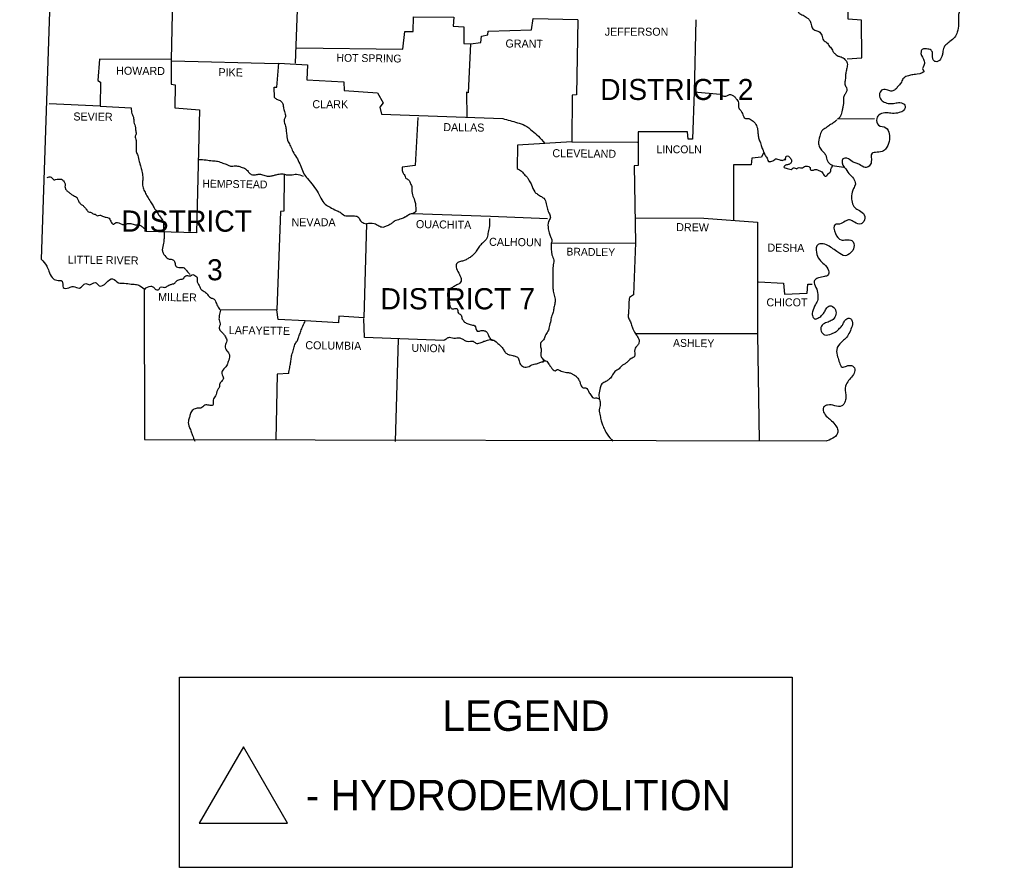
# Model space of a CAD drawing. Extents: x -17668 to 16999, y -17303 to 5867.
# Drawn here: x -17668 to -14783, y 1636 to 4141 of the extents above; entities that cross this region are included whole.
import ezdxf

# ---------------------------------------------------------------- set-up
doc = ezdxf.new("R2010")
doc.units = 0
for name, color, linetype in [('1', 7, 'Continuous'), ('2', 7, 'Continuous'), ('3', 7, 'Continuous'), ('48', 7, 'Continuous')]:
    doc.layers.add(name, color=color, linetype=linetype)

msp = doc.modelspace()

# ---------------------------------------------------------------- linework, layer by layer
at = {"layer": '1'}
msp.add_line((-15250.6, 3847.5), (-15140.6, 3849.1), dxfattribs=at)
for points in [[(-17667.8, 5841.4), (-17553.9, 4926.7), (-17603.4, 3433.6)], [(-15220.9, 4025.3), (-15178, 4028), (-15178.6, 4139.7), (-15218.7, 4142.5), (-15216.5, 4361), (-15251.2, 4365.9), (-15252.3, 4512.9), (-14782.8, 4516.2)], [(-16840.6, 4354.9), (-16853.3, 4012.1)], [(-17213.8, 4294.4), (-17219.8, 4023.6), (-17431.7, 4024.2), (-17436.7, 3961.4), (-17428.9, 3955.9), (-17429.5, 3885.5), (-17579.7, 3892.1)], [(-16849.4, 4057.7), (-16534.6, 4053.3), (-16528.6, 4105.6), (-16503.8, 4105.6), (-16503.3, 4149.6), (-16384.4, 4148), (-16385.5, 4121.6), (-16354.7, 4119.4), (-16354.7, 4070.9), (-16334.8, 4069.3)], [(-16334.8, 4069.3), (-16304, 4073.7), (-16301.8, 4092.4), (-16283.7, 4095.7), (-16282.6, 4106.7), (-16154.3, 4110.6), (-16149.4, 4144.1), (-16017.8, 4141.9)], [(-16017.8, 4140.8), (-16021.1, 3918.5), (-16033.8, 3917.9), (-16035.5, 3779.8)], [(-15668.9, 4140.3), (-15673.3, 3927.3), (-15596.8, 3921.2)], [(-16334.8, 4069.3), (-16341.4, 3925.1), (-16346.4, 3926.7), (-16345.9, 3851.9)], [(-17219.8, 4023.6), (-17219.8, 3950.4), (-17207.7, 3948.2), (-17208.8, 3880), (-17136.2, 3874.5), (-17145, 3510.7), (-17294.7, 3514.5)], [(-17218.7, 4019.8), (-16903.9, 4011.5)], [(-16914.4, 3910.8), (-16915.5, 3941.1), (-16906.7, 3941.6), (-16901.2, 4012.6), (-16816.4, 4007.1), (-16818.6, 3963.6), (-16709.1, 3957.6), (-16708.5, 3931.2), (-16609.5, 3925.1), (-16592.4, 3895.4), (-16602.9, 3882.2), (-16597.9, 3861.8), (-16239.1, 3848.6)], [(-15673.3, 3927.3), (-15678.3, 3787.5), (-15690.9, 3787.5), (-15693.1, 3809), (-15839.5, 3809), (-15839.5, 3778.2)], [(-17429.5, 3885.5), (-17338.1, 3880)], [(-16490, 3851.4), (-16498.3, 3709.9), (-16536.3, 3705.5)], [(-16035.5, 3779.8), (-16115.8, 3774.9)], [(-16035.5, 3779.8), (-15840.6, 3778.7)], [(-16114.7, 3774.9), (-16196.2, 3769.9), (-16196.7, 3701.1)], [(-15839.5, 3778.7), (-15839, 3709.9), (-15850.5, 3709.4), (-15847.2, 3481)], [(-15467.5, 3749.5), (-15474.1, 3734.7), (-15503.3, 3731.9), (-15504.9, 3712.1), (-15557.2, 3712.1), (-15557.7, 3547.6)], [(-15405.8, 3725.3), (-15404.2, 3727), (-15402.5, 3728.6), (-15402.5, 3728.6)], [(-16885.2, 3684.6), (-16886.3, 3575.1), (-16896.2, 3574), (-16907.2, 3283.9)], [(-16503.8, 3568.5), (-16276, 3560.2), (-16107, 3553.6)], [(-15848.9, 3555.8), (-15644.7, 3554.2), (-15486.2, 3542.1)], [(-16642.5, 3537.6), (-16649.6, 3260.3), (-16723.9, 3265.2), (-16724.5, 3244.9), (-16823.6, 3250.9)], [(-15486.2, 3542.1), (-15486.2, 3212.9), (-15481.8, 2896.5)], [(-16096, 3480.4), (-15847.2, 3481)], [(-15847.2, 3481), (-15852.7, 3328), (-15864.8, 3320.3)], [(-15483.4, 3366.5), (-15409.7, 3362.1), (-15406.4, 3330.2), (-15339.8, 3332.4), (-15337.1, 3359.3), (-15324.4, 3359.3)], [(-17299.1, 3345), (-17298, 2899.8), (-15280.9, 2896.5)], [(-16823.6, 3250.9), (-16903.4, 3255.3), (-16907.2, 3283.9), (-17074, 3282.3)], [(-16413.5, 3193.1), (-16648.5, 3201.9), (-16649.6, 3257.5)], [(-15843.9, 3213.5), (-15486.2, 3213.5)], [(-16548.4, 3197), (-16557.2, 2894.8)], [(-16872, 3095.2), (-16906.1, 3093), (-16910, 2899.2)]]:
    msp.add_lwpolyline(points, dxfattribs=at)
for points in [[(-14817.5, 4383), (-14830.2, 4367), (-14848.9, 4376.9), (-14848.9, 4390.1), (-14846.1, 4403.9), (-14852.7, 4412.7), (-14864.3, 4408.9), (-14864.3, 4391.8), (-14865.4, 4375.3), (-14868.7, 4351.6), (-14861, 4344.5), (-14843.4, 4342.3), (-14830.7, 4339), (-14823, 4326.3), (-14823.6, 4310.9), (-14829.6, 4296), (-14838.4, 4283.9), (-14852.2, 4279.5), (-14863.2, 4286.7), (-14867.6, 4301), (-14872.6, 4313.6), (-14881.9, 4323), (-14891.8, 4312.5), (-14894, 4293.3), (-14893.5, 4276.8), (-14893.5, 4254.2), (-14879.2, 4239.3), (-14870.4, 4222.3), (-14873.1, 4206.9), (-14883.6, 4188.7), (-14888, 4172.8), (-14892.4, 4151.3), (-14891.8, 4127.6), (-14895.7, 4104.5), (-14903.4, 4089.1), (-14917.7, 4076.4), (-14927, 4068.2), (-14934.7, 4059.9), (-14938.6, 4043.4), (-14941.3, 4031.9), (-14951.8, 4018.1), (-14960.1, 4017), (-14966.7, 4022.5), (-14968.9, 4031.9), (-14968.9, 4041.2), (-14973.3, 4050.6), (-14987, 4054.4), (-14998, 4053.9), (-15003, 4046.2), (-14995.8, 4024.7), (-14993.1, 4011), (-14996.9, 3992.2), (-14994.7, 3990), (-15014.5, 3979.6), (-15030.5, 3977.9), (-15043.7, 3974.1), (-15056.4, 3965.8), (-15062.4, 3953.7), (-15071.2, 3943.8), (-15078.9, 3934.5), (-15089.4, 3930.1), (-15101, 3932.3), (-15116.4, 3933.9), (-15125.2, 3922.9), (-15122.4, 3906.9), (-15112, 3897.6), (-15096.5, 3893.2), (-15080.6, 3894.3), (-15065.2, 3895.9), (-15050.9, 3888.2), (-15053.6, 3873.4), (-15067.4, 3866.2), (-15087.7, 3864), (-15104.3, 3865.7), (-15124.1, 3861.3), (-15134, 3848.6), (-15128.5, 3829.3), (-15107, 3821.6), (-15097.1, 3803.5), (-15096.5, 3786.4), (-15103.7, 3763.8), (-15113.6, 3753.4), (-15132.9, 3749), (-15147.7, 3746.2), (-15149.9, 3720.9), (-15156.5, 3708.3), (-15168.1, 3704.4), (-15184.6, 3712.7), (-15194.5, 3716.5), (-15206.6, 3722), (-15222, 3731.4), (-15233.6, 3729.7), (-15230.3, 3705.5), (-15229.2, 3704.4), (-15216, 3686.2), (-15202.8, 3671.9), (-15196.7, 3654.9)], [(-15387.7, 4205.8), (-15386, 4183.2), (-15372.8, 4179.9), (-15367.3, 4173.9), (-15364.6, 4161.2), (-15355.2, 4155.7), (-15342.6, 4148), (-15334.9, 4142.5), (-15329.3, 4133.7), (-15326, 4119.4), (-15317.2, 4110), (-15305.1, 4105.6), (-15296.3, 4095.2), (-15290.8, 4080.3), (-15282, 4073.7), (-15273.2, 4062.1), (-15268.8, 4057.2), (-15261.1, 4044), (-15253.4, 4037.4), (-15247.9, 4033.5), (-15239.1, 4030.8), (-15228.1, 4023.6), (-15220.9, 4012.6), (-15220.9, 4004.3), (-15223.7, 3991.7), (-15225.9, 3978.5), (-15227, 3963.6), (-15228.1, 3950.4), (-15223.1, 3939.4), (-15225.9, 3922.9), (-15231.4, 3914.1), (-15231.9, 3902), (-15233.6, 3883.8), (-15235.8, 3873.4), (-15240.7, 3856.3), (-15247.9, 3847.5)], [(-16914.4, 3910.8), (-16905.6, 3905.3), (-16895.1, 3900.3), (-16889.6, 3892.1), (-16887.4, 3879.4), (-16883.5, 3865.7), (-16882.4, 3851.4), (-16885.7, 3843.6), (-16881.3, 3826), (-16879.7, 3813.9), (-16878, 3799.6), (-16873.6, 3780.4), (-16866.5, 3767.1), (-16859.9, 3751.2), (-16848.9, 3734.1), (-16839.5, 3715.4), (-16835.1, 3705.5), (-16826.9, 3685.1), (-16816.4, 3671.4), (-16799.9, 3650.5), (-16785, 3629), (-16776.8, 3613), (-16764.1, 3595.4), (-16749.8, 3586.6), (-16731.6, 3577.3), (-16720.1, 3571.8), (-16706.9, 3562.4), (-16689.8, 3561.3), (-16677.2, 3561.3), (-16665.6, 3556.4), (-16660.1, 3546.5), (-16650.2, 3539.9), (-16642.5, 3537.6)], [(-15596.8, 3921.2), (-15588.6, 3915.7), (-15577, 3916.3), (-15569.3, 3919.6), (-15563.2, 3919), (-15555, 3914.1), (-15549.5, 3907.5), (-15545.6, 3902.5), (-15542.9, 3894.8), (-15542.9, 3887.7), (-15540.1, 3877.8), (-15536.8, 3873.9), (-15532.4, 3866.8), (-15529.7, 3860.2), (-15528, 3855.8), (-15522, 3848.6), (-15516.5, 3849.1), (-15511.5, 3848.6), (-15504.9, 3844.7), (-15495, 3837), (-15493.4, 3834.8), (-15486.7, 3820.5), (-15485.6, 3811.7), (-15484.5, 3800.2), (-15482.3, 3789.2), (-15477.9, 3777.1), (-15475.7, 3768.8), (-15470.8, 3757.2), (-15467.5, 3749.5), (-15463.1, 3739.6), (-15456.5, 3728.6), (-15453.7, 3722), (-15444.4, 3722.6), (-15437.8, 3725.3), (-15432.8, 3729.7), (-15426.8, 3729.2), (-15420.2, 3727), (-15411.4, 3725.3), (-15405.8, 3728.6), (-15403.1, 3730.8), (-15402.5, 3735.8), (-15397.6, 3738.5), (-15392.1, 3734.7), (-15386, 3725.9), (-15386, 3720.4), (-15388.2, 3717.1), (-15395.4, 3712.7), (-15405.3, 3709.4), (-15408, 3705.5), (-15398.7, 3701.1), (-15383.8, 3700), (-15380, 3703.3), (-15370.1, 3700.6), (-15366.2, 3703.3), (-15353, 3702.8), (-15347, 3707.2), (-15334.9, 3706.6), (-15331, 3703.9), (-15331, 3698.9), (-15321.1, 3696.7), (-15313.9, 3698.4), (-15304.6, 3695.6), (-15296.3, 3691.2), (-15291.9, 3685.1), (-15286.4, 3678.5), (-15281.5, 3680.2), (-15277.6, 3685.1), (-15269.4, 3693.9), (-15269.4, 3699.5), (-15267.2, 3703.3), (-15264.4, 3708.8)], [(-17338.1, 3880), (-17335.4, 3863.5), (-17330.4, 3849.1), (-17329.9, 3838.1), (-17324.9, 3821.6), (-17324.9, 3815.6), (-17323.3, 3803.5), (-17325.5, 3796.9), (-17322.7, 3783.7), (-17323.3, 3773.8), (-17323.3, 3765.5), (-17322.7, 3751.7), (-17318.3, 3739.6), (-17313.9, 3721.5), (-17311.2, 3712.1), (-17306.8, 3697.8), (-17304, 3680.2), (-17303.5, 3667), (-17304.6, 3654.9), (-17301.3, 3641.1), (-17295.2, 3627.4), (-17287.5, 3614.1), (-17278.2, 3599.3), (-17271.5, 3587.7), (-17263.3, 3575.1), (-17256.7, 3564.6), (-17246.8, 3551.4), (-17242.4, 3540.4), (-17242.4, 3525), (-17240.2, 3510.7), (-17240.7, 3494.7), (-17241.8, 3480.4), (-17245.7, 3460.6), (-17242.9, 3451.2), (-17232.5, 3437.5), (-17225.9, 3433.6), (-17214.3, 3431.4), (-17208.8, 3423.7), (-17205.5, 3412.2), (-17193.9, 3408.3), (-17181.3, 3407.2), (-17175.2, 3400.6), (-17167, 3391.8), (-17164.2, 3387.4)], [(-16239.1, 3848.6), (-16196.2, 3836.5), (-16174.1, 3828.2), (-16152.1, 3812.3), (-16134, 3796.3), (-16115.8, 3776)], [(-15251.7, 3844.2), (-15263.3, 3834.8), (-15273.2, 3829.3), (-15283.7, 3821.6), (-15296.3, 3812.3), (-15302.4, 3796.3), (-15305.7, 3774.3), (-15301.3, 3761.1), (-15291.4, 3749.5), (-15284.8, 3740.2), (-15279.8, 3723.7), (-15267.7, 3712.1), (-15263.9, 3710.5)], [(-17137.3, 3728.1), (-17116.3, 3726.4), (-17097.1, 3724.2), (-17082.2, 3722.6), (-17066.8, 3717.1), (-17053.1, 3712.1), (-17044.3, 3708.3), (-17029.4, 3709.4), (-17016.7, 3706.6), (-17002.4, 3701.7), (-16992, 3692.3), (-16985.4, 3685.1), (-16972.7, 3682.4), (-16962.2, 3684), (-16949.6, 3682.9), (-16935.3, 3678.5), (-16923.7, 3679.1), (-16914.4, 3681.3), (-16903.4, 3684), (-16889.6, 3685.1), (-16879.1, 3682.9), (-16865.4, 3682.4), (-16849.4, 3684), (-16829.6, 3678.5)], [(-16536.3, 3705.5), (-16536.3, 3695), (-16532.4, 3685.1), (-16528.6, 3680.7), (-16526.9, 3673.6), (-16522, 3670.3), (-16514.8, 3663.7), (-16511, 3654.3), (-16508.2, 3648.3), (-16508.2, 3640.6), (-16507.7, 3632.9), (-16506.6, 3623.5), (-16500, 3607), (-16498.3, 3600.4), (-16497.2, 3594.9), (-16496.6, 3585.5), (-16496.6, 3574.5), (-16503.8, 3568.5)], [(-16196.7, 3701.1), (-16184, 3692.8), (-16173.6, 3681.8), (-16165.9, 3673.6), (-16160.9, 3664.2), (-16154.3, 3653.2), (-16145, 3632.3), (-16136.7, 3625.2), (-16125.2, 3618), (-16118, 3613), (-16110.9, 3597.1), (-16107.5, 3581.1), (-16101.5, 3566.8), (-16098.7, 3555.8), (-16103.7, 3544.8), (-16104.8, 3522.8), (-16101.5, 3507.9), (-16097.1, 3496.9), (-16094.3, 3484.3), (-16096, 3480.4)], [(-17586.3, 3674.7), (-17574.2, 3675.2), (-17566, 3668.1), (-17561, 3668.6), (-17552.2, 3669.7), (-17544, 3669.2), (-17537.9, 3664.2), (-17533, 3655.4), (-17533.5, 3647.2), (-17533, 3643.9), (-17529.1, 3636.7), (-17522.5, 3631.2), (-17515.4, 3625.7), (-17508.7, 3621.3), (-17497.7, 3614.1), (-17496.6, 3611.9), (-17492.2, 3603.1), (-17486.7, 3596), (-17480.1, 3591.6), (-17473, 3583.9), (-17469.7, 3580.6), (-17464.2, 3572.9), (-17458.1, 3572.3), (-17449.9, 3567.4), (-17443.8, 3565.7), (-17437.2, 3561.3), (-17430.6, 3563.5), (-17422.3, 3560.2), (-17411.3, 3556.9), (-17405.3, 3555.8), (-17398.1, 3545.4), (-17391, 3536.5), (-17382.2, 3541.5), (-17365.7, 3536.5), (-17355.2, 3536), (-17345.8, 3538.7), (-17338.7, 3538.2), (-17325.5, 3534.9), (-17317.2, 3534.9), (-17308.4, 3531.6), (-17300.2, 3525), (-17294.7, 3517.8), (-17294.7, 3514.5)], [(-15196.7, 3654.9), (-15202.2, 3642.2), (-15208.3, 3620.2), (-15206.6, 3601.5), (-15198.4, 3585.5), (-15185.2, 3576.7), (-15170.8, 3564.1), (-15171.9, 3544.8), (-15180.2, 3537.6), (-15199.5, 3542.6), (-15214.3, 3549.2), (-15227, 3545.4), (-15244, 3537.1), (-15256.7, 3535.4), (-15256.2, 3509), (-15239.1, 3490.3), (-15224.2, 3490.3), (-15207.2, 3488.1), (-15201.1, 3468.3), (-15211, 3451.8), (-15227.5, 3443.5), (-15248.4, 3453.4), (-15263.3, 3463.9), (-15278.2, 3473.8), (-15296.9, 3478.8), (-15307.3, 3476.6), (-15312.3, 3453.4), (-15303.5, 3432.5), (-15289.2, 3418.2), (-15276, 3399.5), (-15278.2, 3385.8), (-15288.1, 3381.9), (-15305.7, 3378), (-15316.1, 3372.5), (-15318.9, 3368.1), (-15313.4, 3349.4), (-15308.4, 3329.1), (-15308.4, 3313.7), (-15314.5, 3299.3), (-15323.8, 3277.3), (-15322.7, 3263), (-15316.1, 3256.4), (-15307.9, 3258.6), (-15296.9, 3266.3), (-15289.7, 3275.1), (-15283.7, 3286.1), (-15272.1, 3295.5), (-15257.8, 3287.2), (-15254.5, 3270.2), (-15262.8, 3255.3), (-15274.3, 3248.7), (-15288.6, 3243.2), (-15299.1, 3231.1), (-15296.3, 3216.8), (-15288.1, 3209.1), (-15267.7, 3212.9), (-15253.9, 3219), (-15246.2, 3226.7), (-15236.9, 3236.1), (-15231.9, 3245.4), (-15224.8, 3255.3), (-15212.1, 3258.1), (-15206.1, 3249.8), (-15208.3, 3231.1), (-15216, 3213.5), (-15226.4, 3198.6), (-15238, 3188.2), (-15252.3, 3165.6), (-15249.5, 3144.7), (-15244, 3127.6), (-15236.3, 3114.4), (-15223.1, 3117.2), (-15208.3, 3118.8), (-15199.5, 3111.7), (-15200.6, 3096.3), (-15211.6, 3081.4), (-15222, 3067.1), (-15227.5, 3047.3), (-15225.3, 3033.5), (-15225.3, 3020.9), (-15229.7, 3007.1), (-15237.4, 2999.4), (-15257.8, 3000), (-15279.3, 3002.2), (-15290.8, 2995.6), (-15288.6, 2976.8), (-15276, 2963.1), (-15267.2, 2955.9), (-15254.5, 2940.5), (-15249, 2927.9), (-15250.6, 2916.8), (-15258.4, 2907.5), (-15280.9, 2896.5)], [(-16514.3, 3566.3), (-16528.6, 3556.9), (-16539.6, 3552.5), (-16547.8, 3549.8), (-16555.5, 3547.6), (-16565.4, 3541), (-16573.1, 3535.4), (-16583.6, 3530.5), (-16593.5, 3527.2), (-16605.6, 3531), (-16612.2, 3534.9), (-16619.4, 3537.6), (-16642.5, 3537.6)], [(-16528.6, 3556.9), (-16514.3, 3566.3), (-16503.8, 3568.5)], [(-16278.2, 3553.6), (-16279.3, 3526.1), (-16283.1, 3509), (-16287, 3493.6), (-16295.2, 3484.8), (-16304, 3476), (-16312.3, 3466.1), (-16319.4, 3454), (-16326.6, 3446.3), (-16335.9, 3438.6), (-16345.3, 3433.1), (-16355.8, 3428.1), (-16367.3, 3425.4), (-16375.6, 3419.3), (-16376.1, 3406.1), (-16366.8, 3387.4), (-16363.5, 3378.6), (-16362.4, 3368.1), (-16366.2, 3362.1), (-16375, 3357.1), (-16385.5, 3351.1), (-16394.8, 3345.6), (-16401.4, 3336.2), (-16402.5, 3323.6), (-16398.1, 3308.7), (-16396.5, 3299.9), (-16389.3, 3286.1), (-16383.8, 3286.7), (-16373.9, 3286.1), (-16372.8, 3283.4), (-16372.3, 3280.6), (-16370.1, 3273.5), (-16361.8, 3267.4), (-16360.7, 3261.9), (-16355.8, 3251.5), (-16347.5, 3244.3), (-16341.4, 3242.1), (-16328.8, 3238.3), (-16322.2, 3236.6), (-16315, 3220.6), (-16306.2, 3221.2), (-16299.6, 3222.3), (-16288.6, 3219.5), (-16283.7, 3212.9), (-16278.7, 3201.9), (-16272.1, 3194.2), (-16267.7, 3194.2)], [(-16096, 3480.4), (-16093.8, 3446.3), (-16088.8, 3429.8), (-16090.5, 3412.2), (-16091, 3395.1), (-16091, 3379.7), (-16091, 3364.8), (-16091, 3349.4), (-16089.9, 3338.4), (-16086.1, 3322.5), (-16084.4, 3307.6), (-16087.7, 3293.3), (-16089.4, 3280.1), (-16093.8, 3266.9), (-16097.6, 3252), (-16102, 3232.8), (-16105.9, 3220.1), (-16113.6, 3206.9), (-16118.6, 3194.8), (-16126.3, 3187.1), (-16127.4, 3173.9), (-16125.7, 3161.8), (-16126.8, 3150.7), (-16123, 3140.3), (-16113.1, 3133.1)], [(-17603.4, 3433.6), (-17587.5, 3412.7), (-17580.8, 3397.9), (-17571.5, 3378.6), (-17557.7, 3370.9), (-17541.8, 3368.1), (-17538.5, 3349.4), (-17522, 3348.9), (-17508.7, 3352.7), (-17490.6, 3347.8), (-17471.3, 3361), (-17460.3, 3357.7), (-17444.4, 3364.3), (-17432.3, 3354.4), (-17411.3, 3363.2), (-17392.6, 3375.3), (-17375, 3363.7), (-17358, 3362.1), (-17337.6, 3359.3), (-17321.6, 3358.2), (-17307.3, 3351.1), (-17296.9, 3343.9), (-17299.1, 3345)], [(-17299.1, 3345), (-17279.8, 3353.3), (-17271.5, 3350.5), (-17264.4, 3343.4), (-17256.1, 3343.4), (-17251.7, 3350), (-17243.5, 3350.5), (-17236.9, 3350), (-17229.7, 3354.4), (-17223.7, 3357.1), (-17215.4, 3359.9), (-17209.4, 3362.1), (-17203.9, 3368.1), (-17193.9, 3373.1), (-17182.4, 3376.9), (-17179.1, 3382.4), (-17173.6, 3384.7), (-17162.6, 3384.1), (-17155.4, 3387.4), (-17149.4, 3384.7), (-17143.9, 3380.8), (-17142.8, 3366.5), (-17138.4, 3358.8), (-17131.8, 3345), (-17122.4, 3337.9), (-17113.6, 3330.7), (-17110.3, 3326.3), (-17100.9, 3318.1), (-17092.7, 3315.3), (-17088.8, 3309.3), (-17082.8, 3294.9), (-17074, 3282.3)], [(-15864.8, 3320.3), (-15866.5, 3303.2), (-15867, 3287.2), (-15868.1, 3271.8), (-15868.1, 3260.3), (-15861.5, 3247.6), (-15857.7, 3235.5), (-15853.8, 3225), (-15846.1, 3211.3), (-15839, 3200.8), (-15836.8, 3186), (-15841.2, 3178.3), (-15849.4, 3166.7), (-15850, 3145.8), (-15859.9, 3139.2), (-15872.5, 3128.2), (-15879.7, 3123.2), (-15887.4, 3118.3), (-15895.7, 3109.5), (-15907.8, 3101.2), (-15916.6, 3087.5), (-15926.5, 3077), (-15934.7, 3071.5), (-15946.3, 3064.3), (-15951.2, 3053.3), (-15955.1, 3033), (-15953.4, 3018.1), (-15951.2, 3004.9), (-15954, 2988.4), (-15951.2, 2970.2), (-15948.5, 2955.9), (-15944.1, 2943.3), (-15938, 2929), (-15930.3, 2915.7), (-15913.8, 2895.4)], [(-17074, 3282.3), (-17077.3, 3266.3), (-17077.8, 3253.7), (-17075.1, 3238.8), (-17077.8, 3231.7), (-17073.4, 3221.2), (-17065.2, 3212.9), (-17059.1, 3204.1), (-17055.3, 3191.5), (-17060.2, 3177.2), (-17054.7, 3162.3), (-17049.8, 3156.8), (-17047, 3148), (-17050.9, 3130.9), (-17055.8, 3118.3), (-17066.8, 3105.6), (-17070.1, 3099.6), (-17068.5, 3091.3), (-17065.7, 3078.1), (-17068.5, 3074.3), (-17075.6, 3064.9), (-17077.8, 3054.4), (-17082.8, 3045.6), (-17088.3, 3029.7), (-17095.4, 3016.5), (-17096.5, 3001.6), (-17107.5, 3001.6), (-17120.2, 3001.6), (-17131.8, 2993.3), (-17142.2, 2992.8), (-17154.9, 2987.8), (-17162.6, 2977.4), (-17165.3, 2965.8), (-17168.6, 2954.8), (-17165.3, 2936.1), (-17160.4, 2922.9), (-17156.5, 2912.4), (-17149.9, 2895.4)], [(-16872, 3095.2), (-16869.2, 3112.8), (-16866.5, 3126.5), (-16864.8, 3139.7), (-16861.5, 3154.6), (-16856.6, 3170.6), (-16852.2, 3183.8), (-16846.1, 3193.1), (-16842.3, 3204.1), (-16837.3, 3217.3), (-16832.4, 3231.1), (-16823.6, 3248.7)], [(-16413.5, 3193.1), (-16404.7, 3199.2), (-16396.5, 3202.5), (-16388.2, 3200.8), (-16379.4, 3199.7), (-16371.7, 3200.8), (-16361.8, 3199.2), (-16353.6, 3194.2), (-16344.2, 3190.4), (-16334.8, 3190.4), (-16326.6, 3190.4), (-16319.4, 3185.4), (-16306.2, 3186), (-16295.2, 3190.4), (-16284.2, 3193.7), (-16269.4, 3195.3), (-16256.1, 3186), (-16246.8, 3178.3), (-16239.1, 3169.5), (-16233.6, 3159.6), (-16227.5, 3154.1), (-16217.6, 3150.2), (-16209.9, 3148.5), (-16200.6, 3145.8), (-16195.6, 3143.6), (-16191.2, 3133.1), (-16184, 3118.8), (-16170.3, 3113.9), (-16153.2, 3120.5), (-16139.5, 3124.3), (-16129.6, 3127.6), (-16123.5, 3129.8), (-16118, 3130.4), (-16119.7, 3131.5), (-16113.1, 3133.1), (-16107, 3128.7), (-16103.1, 3122.7), (-16096.5, 3113.9), (-16090.5, 3106.2), (-16084.4, 3103.4), (-16078.4, 3106.7), (-16070.1, 3104), (-16063, 3101.2), (-16054.7, 3099), (-16047.6, 3098.5), (-16038.2, 3096.3), (-16031, 3092.4), (-16024.4, 3088.6), (-16017.8, 3081.4), (-16011.2, 3070.4), (-16009, 3061.6), (-16001.3, 3052.8), (-15994.2, 3052.8), (-15983.7, 3038.5), (-15979.9, 3033), (-15971.6, 3023.1), (-15965.6, 3023.1), (-15954, 3020.9)]]:
    msp.add_spline(points, degree=3, dxfattribs=at)
at = {"layer": '3'}
msp.add_line((-15265.5, 3709.9), (-15230.8, 3705.5), dxfattribs=at)
at = {"layer": '48'}
for p, q in [((-17005.9, 1992.2), (-17136.5, 1766)), ((-16875.3, 1766), (-17005.9, 1992.2)), ((-17136.5, 1766), (-16875.3, 1766))]:
    msp.add_line(p, q, dxfattribs=at)
msp.add_lwpolyline([(-17194.5, 2198.1), (-15383.9, 2198.1), (-15383.9, 1635.5), (-17194.5, 1635.5)], close=True, dxfattribs=at)

# ---------------------------------------------------------------- texts
at = {"layer": '2'}
for s, height, p in [('JEFFERSON', 23.67, (-15938, 4093.5)), ('CLARK', 23.67, (-16802, 3879.3)), ('LINCOLN', 23.11, (-15785, 3746.2)), ('NEVADA', 23.67, (-16863.7, 3530.5)), ('CHICOT', 23.67, (-15459.8, 3293.8))]:
    msp.add_text(s, height=height, dxfattribs=at).set_placement(p)
for s, height, rotation, p in [('GRANT', 23.67, 359.4032, (-16231.4, 4058.8)), ('HOT SPRING', 23.11, 359.2216, (-16731.1, 4017)), ('HOWARD', 23.67, 359.5145, (-17382.2, 3978.5)), ('PIKE', 23.66, 359.0452, (-17080, 3974.1)), ('SEVIER', 23.67, 359.4271, (-17508.7, 3843.1)), ('DALLAS', 23.66, 359.2462, (-16415.2, 3811.7)), ('CLEVELAND', 23.67, 359.3377, (-16092.7, 3734.7)), ('HEMPSTEAD', 23.11, 359.1885, (-17127.4, 3645)), ('OUACHITA', 23.67, 359.2043, (-16496.1, 3525)), ('DREW', 23.66, 359.2258, (-15726.7, 3516.2)), ('CALHOUN', 23.67, 359.3634, (-16279.8, 3472.7)), ('BRADLEY', 23.11, 359.1449, (-16051.4, 3444.1)), ('DESHA', 23.66, 359.3704, (-15457, 3455.6)), ('LITTLE RIVER', 23.666, 359.1697, (-17525.3, 3420.4)), ('MILLER', 23.66, 359.1319, (-17258.3, 3309.8)), ('LAFAYETTE', 23.66, 359.1839, (-17049.2, 3211.8)), ('COLUMBIA', 23.66, 359.2125, (-16823, 3167.3)), ('UNION', 23.11, 358.9584, (-16509.3, 3159.6)), ('ASHLEY', 23.11, 359.2361, (-15736.1, 3174.4))]:
    msp.add_text(s, height=height, rotation=rotation, dxfattribs=at).set_placement(p)
at = {"layer": '3'}
for s, height, p in [('DISTRICT 2', 62.19, (-15951.2, 3903.6)), ('DISTRICT', 62.74, (-17367.1, 3514.4)), ('3', 62.2, (-17113.4, 3370.8)), ('DISTRICT 7', 62.74, (-16600.8, 3284.8))]:
    msp.add_text(s, height=height, dxfattribs=at).set_placement(p)
at = {"layer": '48'}
for s, p in [('LEGEND', (-16418.3, 2039.2)), ('- HYDRODEMOLITION', (-16821.7, 1804.3))]:
    msp.add_text(s, height=90, dxfattribs=at).set_placement(p)

doc.saveas('drawing.dxf')
